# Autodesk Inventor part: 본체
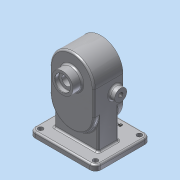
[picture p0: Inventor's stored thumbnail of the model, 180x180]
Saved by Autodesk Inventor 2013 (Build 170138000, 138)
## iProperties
Created: 2020-09
Part Number: 본체
Material: 알루미늄 6061
Document SubType Name: Modeling
Designer: Administrator
Density: 2.71 g/cm^3
Mass: 1445.81 g
Surface Area: 785.637 cm^2
Volume: 533.508 cm^3
Author: Administrator
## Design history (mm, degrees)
sketch "스케치1"
  geometry: L1 (-40, -62)-(40, -62); L2 (40, -62)-(40, 62); L3 (40, 62)-(-40, 62); L4 (-40, 62)-(-40, -62); L5 (-40, -62)-(40, 62); L6 (40, -62)-(-40, 62); 3 further points
  constraints: 12 end point, 3 midpoint, 2 parallel, 1 coincident, 1 horizontal, 1 perpendicular
  dimensions: "d0" = 124 distance of L1.end L2.end; "d2" = 80 distance of L1.start L1.end
extrude "돌출1" new body sketch "스케치1" distance "d3" = 53; taper "d4" = 0 deg
fillet "모깎기1" dims "d5" = 40
sketch "스케치2"
  geometry: L1 (0, 22)-(0, -22); L2 (24, 22)-(24, -22); L3 (-24, -22)-(-24, 22); A1 r 24 centre (0, -22) between (-24, -22) and (24, -22); A2 r 24 centre (0, 22) between (24, 22) and (-24, 22); 2 further points
  constraints: 6 end point, 4 point on circle, 3 coincident, 2 centre point, 2 parallel, 2 tangent, 1 midpoint, 1 vertical
  dimensions: "d7" = 44 distance of L1.start L1.end
extrude "돌출2" cut sketch "스케치2" distance "d11" = 29; taper "d12" = 0 deg
sketch "스케치3"
  geometry: L1 (-53, 44)-(0, 44) reference; L2 (0, 0)-(0, 44) reference; L3 (-53, 0)-(-53, 44) reference; C1 r 11 at (-39, 22); 3 further points
  constraints: 2 midpoint, 1 centre point, 1 horizontal alignment
  dimensions: "d13" = 22 diameter of C1; "d63" = 14 distance from line of L3 C1.centre
extrude "돌출3" join sketch "스케치3" distance "d15" = 10; taper "d16" = 0 deg
sketch "스케치4"
  geometry: L1 (0, 44)-(53, 44) reference; L2 (0, 44)-(0, 0) reference; L3 (53, 44)-(53, 0) reference; C1 r 11 at (39, 22); 3 further points
  constraints: 2 midpoint, 1 centre point, 1 horizontal alignment
  dimensions: "d17" = 22 diameter of C1; "d64" = 14 distance from line of L3 C1.centre
extrude "돌출4" join sketch "스케치4" distance "d19" = 10; taper "d20" = 0 deg
sketch "스케치5"
  geometry: L1 (-40, -22)-(-40, 22) reference; L2 (-40, 0)-(39.368, 0); C1 r 19 at (0, 22); 1 further point
  constraints: 2 end point, 1 centre point, 1 midpoint, 1 perpendicular
  dimensions: "d21" = 38 diameter of C1; "d23" = 22 distance from line of C1.centre L2
extrude "돌출5" join sketch "스케치5" distance "d24" = 17; taper "d25" = 0 deg
node "작업 평면1"
sketch "스케치6"
  geometry: L1 (-19, -17)-(19, -17) reference; L2 (-60, 83)-(-60, -17); L3 (-60, -17)-(60, -17); L4 (60, -17)-(60, 83); L5 (60, 83)-(-60, 83); L6 (-60, 83)-(60, -17); L7 (-60, -17)-(60, 83); 5 further points
  constraints: 12 end point, 5 midpoint, 2 parallel, 2 perpendicular, 1 coincident, 1 vertical alignment
  dimensions: "d27" = 120 distance of L4.end L2.start; "d29" = 100 distance of L3.end L4.end
extrude "돌출6" join sketch "스케치6" distance "d30" = 10; taper "d31" = 0 deg
sketch "스케치7"
  geometry: L1 (40, -53)-(40, 0) reference; L2 (-40, 0)-(-40, -53) reference; L3 (-40, -45)-(40, -45); L4 (40, -45)-(40, -8); L5 (40, -8)-(-40, -8); L6 (-40, -8)-(-40, -45); L7 (-40, -45)-(40, -8); L8 (40, -45)-(-40, -8); L9 (60, 17)-(-60, 17) reference; 3 further points
  constraints: 12 end point, 4 midpoint, 2 parallel, 2 perpendicular, 1 vertical alignment
  dimensions: "d35" = 25 distance between parallel lines of L9 L5; "d36" = 80 distance of L4.end L5.end; "d37" = 37 distance of L3.end L4.end
extrude "돌출7" join sketch "스케치7" stored distance "d38" = 10; taper "d39" = 0 deg
fillet "모깎기2" dims "d40" = 10
fillet "모깎기3" dims "d41" = 3
fillet "모깎기4" dims "d42" = 3
fillet "모깎기5" dims "d43" = 3
fillet "모깎기6" dims "d44" = 3
fillet "모깎기7" dims "d45" = 3
sketch "스케치8"
  geometry: L1 (0, 22)-(0, -22); C1 r 12.5 at (0, -22); C2 r 12.5 at (0, 22); 2 further points
  constraints: 3 coincident, 2 centre point, 2 end point, 1 midpoint, 1 vertical
  dimensions: "d46" = 44 distance of L1.start L1.end; "d48" = 25 diameter of C1; "d49" = 25 diameter of C2
extrude "돌출8" cut sketch "스케치8" distance "d50" = 15; taper "d51" = 0 deg
sketch "스케치9"
  geometry: C1 r 19 at (0, 0) reference; C2 r 14 at (0, 0); 1 further point
  constraints: 1 centre point, 1 coincident
  dimensions: "d52" = 28 diameter of C2
extrude "돌출9" cut sketch "스케치9" distance "d54" = 7.3; taper "d55" = 0 deg
chamfer "모따기1" distance "d56" = 0.7; stored, may be unused: second distance "d57" = 2, angle "d58" = 30 deg
sketch "스케치10"
  geometry: C1 r 19 at (0, 0) reference; C2 r 8.5 at (0, 0); 1 further point
  constraints: 1 centre point, 1 coincident
  dimensions: "d59" = 17 diameter of C2
extrude "돌출10" cut sketch "스케치10" stored distance "d61" = 7.3; taper "d62" = 0 deg
sketch "스케치11"
  geometry: C1 r 11 at (0, 0) reference; 2 further points
  constraints: 1 coincident
hole "구멍1" sketch "스케치11" at (0, 0) diameter "d65" = 8.376; stored, may be unused: countersink angle "d69" = 90 deg, drill point angle "d71" = 118 deg; dims "d66" = 30, "d67" = 4, "d68" = 2, "d70" = 31
sketch "스케치12"
  geometry: C1 r 11 at (0, 0) reference; 2 further points
  constraints: 1 coincident
hole "구멍2" sketch "스케치12" at (0, 0) diameter "d72" = 8.376; stored, may be unused: countersink angle "d76" = 90 deg, drill point angle "d78" = 118 deg; dims "d73" = 30, "d74" = 4, "d75" = 2, "d77" = 31
fillet "모깎기8" dims "d79" = 0.5
chamfer "모따기2" distance "d80" = 1; stored, may be unused: second distance "d81" = 2, angle "d82" = 30 deg
hole "구멍3" diameter "d85" = 9; stored, may be unused: countersink angle "d89" = 90 deg, drill point angle "d91" = 0 deg; dims "d83" = 10, "d84" = 10, "d86" = 30, "d87" = 4, "d88" = 2, "d90" = 31
hole "구멍4" diameter "d94" = 9; stored, may be unused: countersink angle "d98" = 90 deg, drill point angle "d100" = 0 deg; dims "d92" = 10, "d93" = 10, "d95" = 30, "d96" = 4, "d97" = 2, "d99" = 31
hole "구멍5" diameter "d103" = 9; stored, may be unused: countersink angle "d107" = 90 deg, drill point angle "d109" = 0 deg; dims "d101" = 10, "d102" = 10, "d104" = 30, "d105" = 4, "d106" = 2, "d108" = 31
hole "구멍6" diameter "d112" = 9; stored, may be unused: countersink angle "d116" = 90 deg, drill point angle "d118" = 0 deg; dims "d110" = 10, "d111" = 10, "d113" = 30, "d114" = 4, "d115" = 2, "d117" = 31
sketch "스케치13"
  geometry: A1 r 24 centre (0, 22) between (24, 22) and (-24, 22) reference; A2 r 31 centre (0, 22) between (0, 53) and (31, 22); A3 r 24 centre (0, -22) between (-24, -22) and (24, -22) reference; A4 r 31 centre (0, -22) between (31, -22) and (-31, -22); 3 further points
  constraints: 6 point on circle, 4 horizontal alignment, 2 centre point, 2 coincident, 2 vertical alignment
  dimensions: "d119" = 62 diameter of A2; "d123" = 62 diameter of A4
hole "구멍7" sketch "스케치13" at (0, 53), (31, 22), (-31, 22), (31, -22), (-31, -22), (0, -53) diameter "d124" = 4.134; stored, may be unused: countersink angle "d128" = 90 deg, drill point angle "d130" = 118 deg; dims "d125" = 10, "d126" = 4, "d127" = 2, "d129" = 12
fillet "모깎기9" dims "d131" = 3
sketch "스케치14"
  geometry: L1 (-50, -83)-(50, -83) reference; L2 (-60, 7)-(-60, -73) reference; 2 further points
  constraints: 1 other
  dimensions: "d132" = 12 distance from line of L1 point (0, -71); "d133" = 60 distance from line of L2 point (0, -71)
feature "엠보싱1" sketch "스케치14" dims "d11" = 29, "d134" = 0.5, "d135" = 0
node "솔리드1"
other parameters: "d9" = 48, "d10" = 48
